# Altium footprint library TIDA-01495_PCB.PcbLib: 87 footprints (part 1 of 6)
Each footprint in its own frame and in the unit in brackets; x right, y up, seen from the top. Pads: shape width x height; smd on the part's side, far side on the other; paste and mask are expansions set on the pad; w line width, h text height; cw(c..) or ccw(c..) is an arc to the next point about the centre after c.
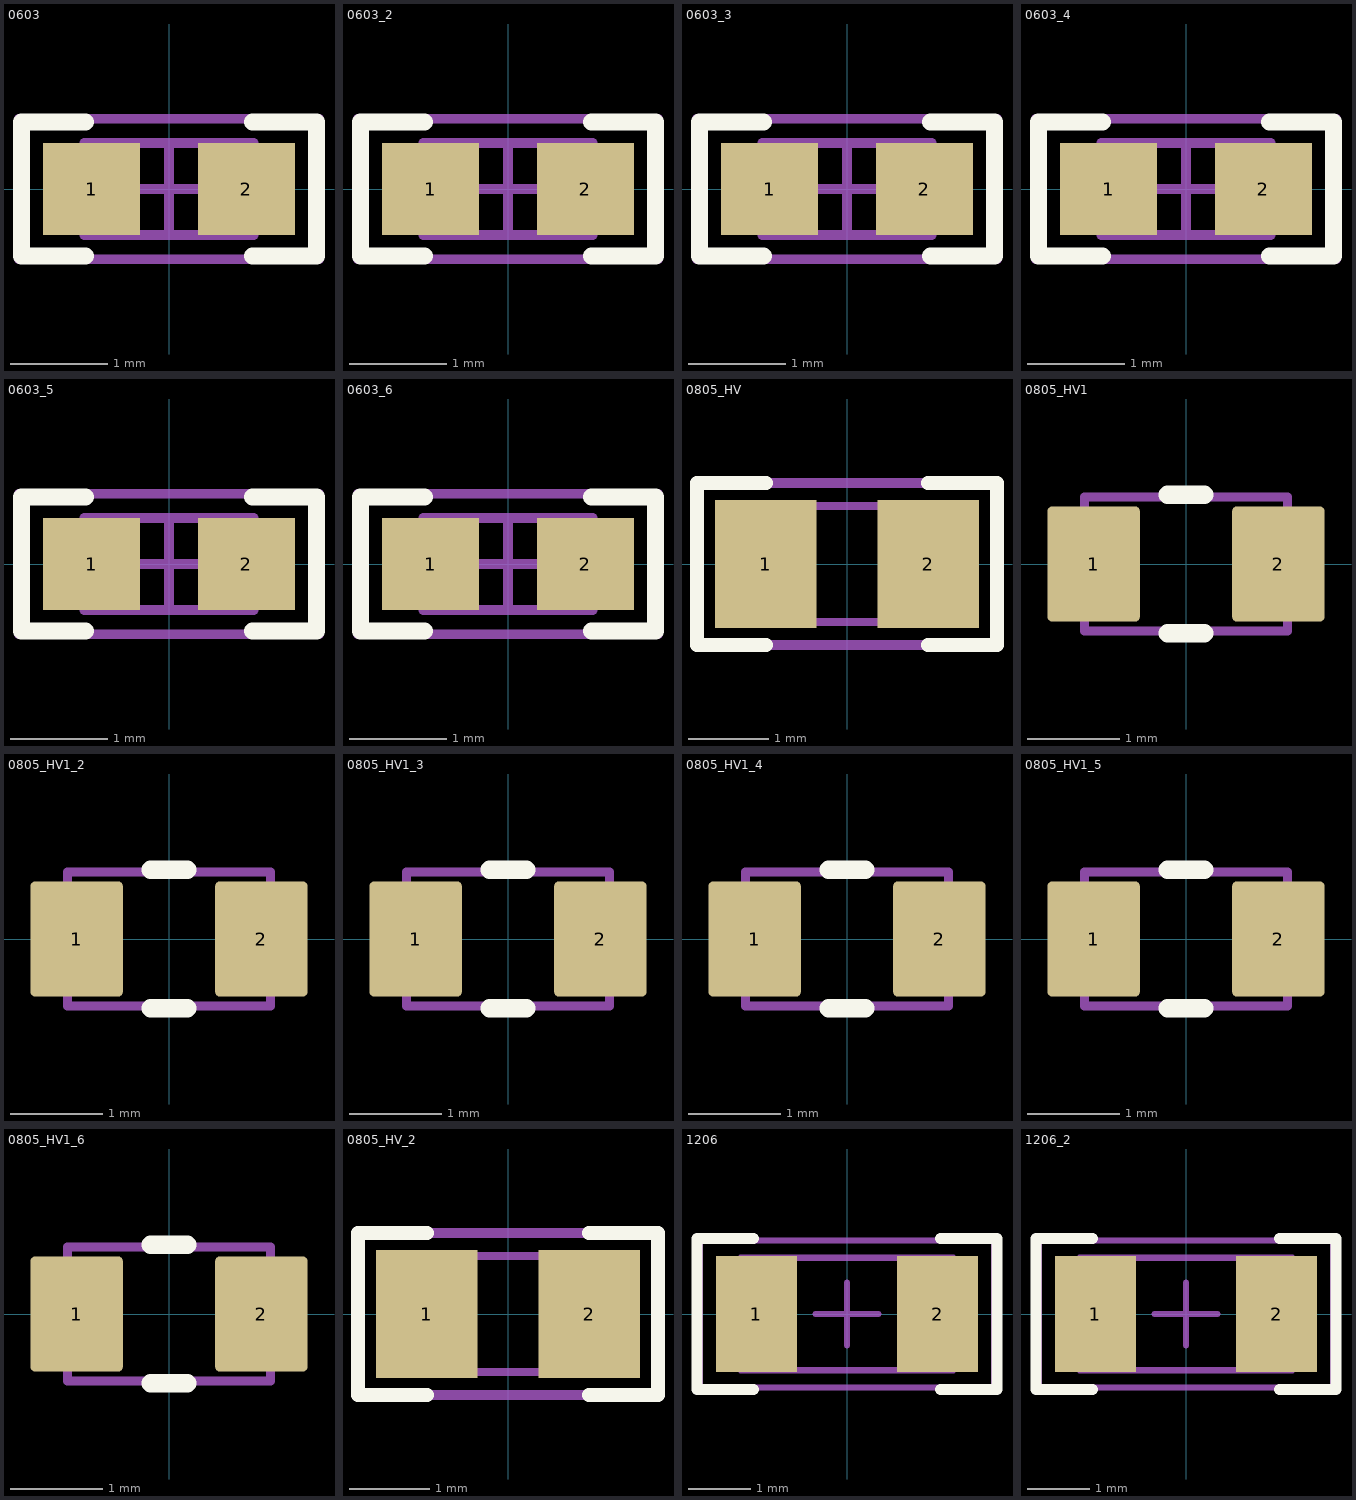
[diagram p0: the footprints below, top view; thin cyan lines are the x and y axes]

## 0603 [mm] "0603 from SM-752 data"
height 1
pads (2):
  rect 1x0.95 smd: 1(-0.8,0) 2(0.8,0)
Top Overlay:
  lines w0.178: -0.864,-0.691 -1.524,-0.691 -1.524,0.693 -0.864,0.693 ; 0.864,-0.691 1.524,-0.691 1.524,0.693 0.864,0.693
Mechanical 5:
  lines w0.1: -1.55,-0.725 -1.55,0.725 1.55,0.725 1.55,-0.725 -1.55,-0.725
  text ".Designator" at -1.397,-0.381 h0.76
Mechanical 13:
  lines w0.1: -0.55,-0.475 -0.55,0.475 ; 0.55,-0.475 0.55,0.475 ; -0.875,-0.475 0.875,-0.475 0.875,0.475 -0.875,0.475 -0.875,-0.475
Mechanical 15:
  lines w0.1: -0.475,0 0.475,0 ; 0,-0.475 0,0.475 ; -1.55,-0.725 1.55,-0.725 1.55,0.725 -1.55,0.725 -1.55,-0.725
3D body: height 1, standoff 0, extent -0.874,-0.474 -0.551,0.474
3D body: height 1, standoff 0, extent -0.549,-0.474 0.549,0.474
3D body: height 1, standoff 0, extent 0.551,-0.474 0.874,0.474

## 0603_2 [mm]
pads (2):
  rect 1x0.95 smd: 1(-0.8,0) 2(0.8,0)
Top Overlay:
  lines w0.178: -0.864,-0.691 -1.524,-0.691 -1.524,0.693 -0.864,0.693 ; 0.864,-0.691 1.524,-0.691 1.524,0.693 0.864,0.693
Mechanical 5:
  lines w0.1: -1.55,-0.725 1.55,-0.725 1.55,0.725 -1.55,0.725 -1.55,-0.725
  text ".Designator" at -1.121,-0.395 h0.76
Mechanical 13:
  lines w0.1: -0.55,-0.475 -0.55,0.475 ; 0.55,-0.475 0.55,0.475 ; -0.875,-0.475 -0.875,0.475 0.875,0.475 0.875,-0.475 -0.875,-0.475
Mechanical 15:
  lines w0.1: -0.475,0 0.475,0 ; 0,-0.475 0,0.475 ; -1.55,-0.725 -1.55,0.725 1.55,0.725 1.55,-0.725 -1.55,-0.725
3D body: height 1, standoff 0, extent 0.551,-0.474 0.874,0.474
3D body: height 1, standoff 0, extent -0.549,-0.474 0.549,0.474
3D body: height 1, standoff 0, extent -0.874,-0.474 -0.551,0.474

## 0603_3 [mm]
pads (2):
  rect 1x0.95 smd: 1(-0.8,0) 2(0.8,0)
Top Overlay:
  lines w0.178: -0.864,-0.691 -1.524,-0.691 -1.524,0.693 -0.864,0.693 ; 0.864,-0.691 1.524,-0.691 1.524,0.693 0.864,0.693
Mechanical 5:
  lines w0.1: -1.55,-0.725 1.55,-0.725 1.55,0.725 -1.55,0.725 -1.55,-0.725
  text ".Designator" at 0.96,0.394 h0.76
Mechanical 13:
  lines w0.1: -0.55,-0.475 -0.55,0.475 ; 0.55,-0.475 0.55,0.475 ; -0.875,-0.475 -0.875,0.475 0.875,0.475 0.875,-0.475 -0.875,-0.475
Mechanical 15:
  lines w0.1: -0.475,0 0.475,0 ; 0,-0.475 0,0.475 ; -1.55,-0.725 -1.55,0.725 1.55,0.725 1.55,-0.725 -1.55,-0.725
3D body: height 1, standoff 0, extent 0.551,-0.474 0.874,0.474
3D body: height 1, standoff 0, extent -0.549,-0.474 0.549,0.474
3D body: height 1, standoff 0, extent -0.874,-0.474 -0.551,0.474

## 0603_4 [mm]
pads (2):
  rect 1x0.95 smd: 1(-0.8,0) 2(0.8,0)
Top Overlay:
  lines w0.178: -0.864,-0.691 -1.524,-0.691 -1.524,0.693 -0.864,0.693 ; 0.864,-0.691 1.524,-0.691 1.524,0.693 0.864,0.693
Mechanical 5:
  lines w0.1: -1.55,-0.725 1.55,-0.725 1.55,0.725 -1.55,0.725 -1.55,-0.725
  text ".Designator" at 1.267,0.473 h0.89
Mechanical 13:
  lines w0.1: -0.55,-0.475 -0.55,0.475 ; 0.55,-0.475 0.55,0.475 ; -0.875,-0.475 -0.875,0.475 0.875,0.475 0.875,-0.475 -0.875,-0.475
Mechanical 15:
  lines w0.1: -0.475,0 0.475,0 ; 0,-0.475 0,0.475 ; -1.55,-0.725 -1.55,0.725 1.55,0.725 1.55,-0.725 -1.55,-0.725
3D body: height 1, standoff 0, extent 0.551,-0.474 0.874,0.474
3D body: height 1, standoff 0, extent -0.549,-0.474 0.549,0.474
3D body: height 1, standoff 0, extent -0.874,-0.474 -0.551,0.474

## 0603_5 [mm]
pads (2):
  rect 1x0.95 smd: 1(-0.8,0) 2(0.8,0)
Top Overlay:
  lines w0.178: -0.864,-0.691 -1.524,-0.691 -1.524,0.693 -0.864,0.693 ; 0.864,-0.691 1.524,-0.691 1.524,0.693 0.864,0.693
Mechanical 5:
  lines w0.1: -1.55,-0.725 -1.55,0.725 1.55,0.725 1.55,-0.725 -1.55,-0.725
  text ".Designator" at 1.054,0.366 h0.76
Mechanical 13:
  lines w0.1: -0.55,-0.475 -0.55,0.475 ; 0.55,-0.475 0.55,0.475 ; -0.875,-0.475 0.875,-0.475 0.875,0.475 -0.875,0.475 -0.875,-0.475
Mechanical 15:
  lines w0.1: -0.475,0 0.475,0 ; 0,-0.475 0,0.475 ; -1.55,-0.725 1.55,-0.725 1.55,0.725 -1.55,0.725 -1.55,-0.725
3D body: height 1, standoff 0, extent -0.874,-0.474 -0.551,0.474
3D body: height 1, standoff 0, extent -0.549,-0.474 0.549,0.474
3D body: height 1, standoff 0, extent 0.551,-0.474 0.874,0.474

## 0603_6 [mm]
pads (2):
  rect 1x0.95 smd: 1(-0.8,0) 2(0.8,0)
Top Overlay:
  lines w0.178: -0.864,-0.691 -1.524,-0.691 -1.524,0.693 -0.864,0.693 ; 0.864,-0.691 1.524,-0.691 1.524,0.693 0.864,0.693
Mechanical 5:
  lines w0.1: -1.55,-0.725 1.55,-0.725 1.55,0.725 -1.55,0.725 -1.55,-0.725
  text ".Designator" at -1.194,-0.458 h0.89
Mechanical 13:
  lines w0.1: -0.55,-0.475 -0.55,0.475 ; 0.55,-0.475 0.55,0.475 ; -0.875,-0.475 -0.875,0.475 0.875,0.475 0.875,-0.475 -0.875,-0.475
Mechanical 15:
  lines w0.1: -0.475,0 0.475,0 ; 0,-0.475 0,0.475 ; -1.55,-0.725 -1.55,0.725 1.55,0.725 1.55,-0.725 -1.55,-0.725
3D body: height 1, standoff 0, extent 0.551,-0.474 0.874,0.474
3D body: height 1, standoff 0, extent -0.549,-0.474 0.549,0.474
3D body: height 1, standoff 0, extent -0.874,-0.474 -0.551,0.474

## 0805_HV [mil] "0805 with 30mil clearance between pads"
height 57.09
pads (2):
  rect 50x63 smd: 1(-40,0) 2(40,0)
Top Overlay:
  lines w7: -40,-40 -74,-40 -74,0 -74,40 -40,40 ; 40,-40 74,-40 74,0 74,40 40,40
Mechanical 5:
  lines w5: -74,-40 74,-40 74,40 -74,40 -74,-40
  text ".Designator" at -47.92,-16.07 h35
Mechanical 13:
  lines w3.94: -25.59,-28.54 -25.59,28.54 ; 25.59,-28.54 25.59,28.54 ; -43.31,-28.54 43.31,-28.54 43.31,28.54 -43.31,28.54 -43.31,-28.54
3D body: height 57.09, standoff 0, extent -43.29,-28.52 -25.61,28.52
3D body: height 57.09, standoff 0, extent -25.57,-28.52 25.57,28.52
3D body: height 57.09, standoff 0, extent 25.61,-28.52 43.29,28.52

## 0805_HV1 [mm] "Custom footprint based on analyzing multiple manufacturer recommendations"
height 1.45
pads (2):
  rrect10% 1x1.25 smd: 1(-1,0) 2(1,0)
Top Overlay:
  lines w0.2: -0.2,-0.75 0.2,-0.75 ; -0.2,0.75 0.2,0.75
Mechanical 5:
  lines w0.1: -1.1,-0.725 -1.1,0.725 1.1,0.725 1.1,-0.725 -1.1,-0.725
  text ".Designator" at -0.925,-0.25 h0.51
3D body "0805_CapMax.stp": height 1.45, standoff 0, extent -1.1,-0.725 1.1,0.725

## 0805_HV1_2 [mm]
pads (2):
  rrect10% 1x1.25 smd: 1(-1,0) 2(1,0)
Top Overlay:
  lines w0.2: -0.2,-0.75 0.2,-0.75 ; -0.2,0.75 0.2,0.75
Mechanical 5:
  lines w0.1: -1.1,-0.725 1.1,-0.725 1.1,0.725 -1.1,0.725 -1.1,-0.725
  text ".Designator" at -0.925,-0.25 h0.51
3D body "0805_CapMax.stp": height 1.45, standoff 0, extent -1.1,-0.725 1.1,0.725

## 0805_HV1_3 [mm]
pads (2):
  rrect10% 1x1.25 smd: 1(-1,0) 2(1,0)
Top Overlay:
  lines w0.2: -0.2,-0.75 0.2,-0.75 ; -0.2,0.75 0.2,0.75
Mechanical 5:
  lines w0.1: -1.1,-0.725 -1.1,0.725 1.1,0.725 1.1,-0.725 -1.1,-0.725
  text ".Designator" at -0.711,-0.198 h0.51
3D body "0805_CapMax.stp": height 1.45, standoff 0, extent -1.1,-0.725 1.1,0.725

## 0805_HV1_4 [mm]
pads (2):
  rrect10% 1x1.25 smd: 1(-1,0) 2(1,0)
Top Overlay:
  lines w0.2: -0.2,-0.75 0.2,-0.75 ; -0.2,0.75 0.2,0.75
Mechanical 5:
  lines w0.1: -1.1,-0.725 -1.1,0.725 1.1,0.725 1.1,-0.725 -1.1,-0.725
  text ".Designator" at -0.728,-0.308 h0.51
3D body "0805_CapMax.stp": height 1.45, standoff 0, extent -1.1,-0.725 1.1,0.725

## 0805_HV1_5 [mm]
pads (2):
  rrect10% 1x1.25 smd: 1(-1,0) 2(1,0)
Top Overlay:
  lines w0.2: -0.2,-0.75 0.2,-0.75 ; -0.2,0.75 0.2,0.75
Mechanical 5:
  lines w0.1: -1.1,-0.725 -1.1,0.725 1.1,0.725 1.1,-0.725 -1.1,-0.725
  text ".Designator" at -0.738,-0.253 h0.51
3D body "0805_CapMax.stp": height 1.45, standoff 0, extent -1.1,-0.725 1.1,0.725

## 0805_HV1_6 [mm]
pads (2):
  rrect10% 1x1.25 smd: 1(-1,0) 2(1,0)
Top Overlay:
  lines w0.2: -0.2,-0.75 0.2,-0.75 ; -0.2,0.75 0.2,0.75
Mechanical 5:
  lines w0.1: -1.1,-0.725 -1.1,0.725 1.1,0.725 1.1,-0.725 -1.1,-0.725
  text ".Designator" at 0.658,0.269 h0.51
3D body "0805_CapMax.stp": height 1.45, standoff 0, extent -1.1,-0.725 1.1,0.725

## 0805_HV_2 [mil]
pads (2):
  rect 50x63 smd: 1(-40,0) 2(40,0)
Top Overlay:
  lines w7: -40,-40 -74,-40 -74,0 -74,40 -40,40 ; 40,-40 74,-40 74,0 74,40 40,40
Mechanical 5:
  lines w5: -74,-40 -74,40 74,40 74,-40 -74,-40
  text ".Designator" at -30.79,-16.82 h35
Mechanical 13:
  lines w3.94: -25.59,-28.54 -25.59,28.54 ; 25.59,-28.54 25.59,28.54 ; -43.31,-28.54 -43.31,28.54 43.31,28.54 43.31,-28.54 -43.31,-28.54
3D body: height 57.09, standoff 0, extent 25.61,-28.52 43.29,28.52
3D body: height 57.09, standoff 0, extent -25.57,-28.52 25.57,28.52
3D body: height 57.09, standoff 0, extent -43.29,-28.52 -25.61,28.52

## 1206 [mm] "1206 from SM-752 data"
height 1.35
pads (2):
  rect 1.3x1.85 smd: 1(-1.45,0) 2(1.45,0)
Top Overlay:
  lines w0.178: -1.5,-1.21 -2.4,-1.21 -2.4,1.21 -1.5,1.21 ; 1.5,-1.21 2.4,-1.21 2.4,1.21 1.5,1.21
Mechanical 5:
  lines w0.1: -1.7,-0.9 1.7,-0.9 1.7,0.9 -1.7,0.9 -1.7,-0.9
  text ".Designator" at 0.632,0.389 h0.81
Mechanical 13:
  lines w0.1: -1.2,-0.9 -1.2,0.9 ; 1.2,-0.9 1.2,0.9 ; -1.7,-0.9 1.7,-0.9 1.7,0.9 -1.7,0.9 -1.7,-0.9
Mechanical 15:
  lines w0.1: -0.5,0 0.5,0 ; 0,-0.5 0,0.5 ; -2.35,-1.175 2.35,-1.175 2.35,1.175 -2.35,1.175 -2.35,-1.175
3D body: height 1.35, standoff 0, extent -1.699,-0.899 -1.201,0.899
3D body: height 1.35, standoff 0, extent -1.199,-0.899 1.199,0.899
3D body: height 1.35, standoff 0, extent 1.201,-0.899 1.699,0.899

## 1206_2 [mm]
pads (2):
  rect 1.3x1.85 smd: 1(-1.45,0) 2(1.45,0)
Top Overlay:
  lines w0.178: -1.5,-1.21 -2.4,-1.21 -2.4,1.21 -1.5,1.21 ; 1.5,-1.21 2.4,-1.21 2.4,1.21 1.5,1.21
Mechanical 5:
  lines w0.1: -1.7,-0.9 -1.7,0.9 1.7,0.9 1.7,-0.9 -1.7,-0.9
  text ".Designator" at -1.16,-0.403 h0.89
Mechanical 13:
  lines w0.1: -1.2,-0.9 -1.2,0.9 ; 1.2,-0.9 1.2,0.9 ; -1.7,-0.9 -1.7,0.9 1.7,0.9 1.7,-0.9 -1.7,-0.9
Mechanical 15:
  lines w0.1: -0.5,0 0.5,0 ; 0,-0.5 0,0.5 ; -2.35,-1.175 -2.35,1.175 2.35,1.175 2.35,-1.175 -2.35,-1.175
3D body: height 1.35, standoff 0, extent 1.201,-0.899 1.699,0.899
3D body: height 1.35, standoff 0, extent -1.199,-0.899 1.199,0.899
3D body: height 1.35, standoff 0, extent -1.699,-0.899 -1.201,0.899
